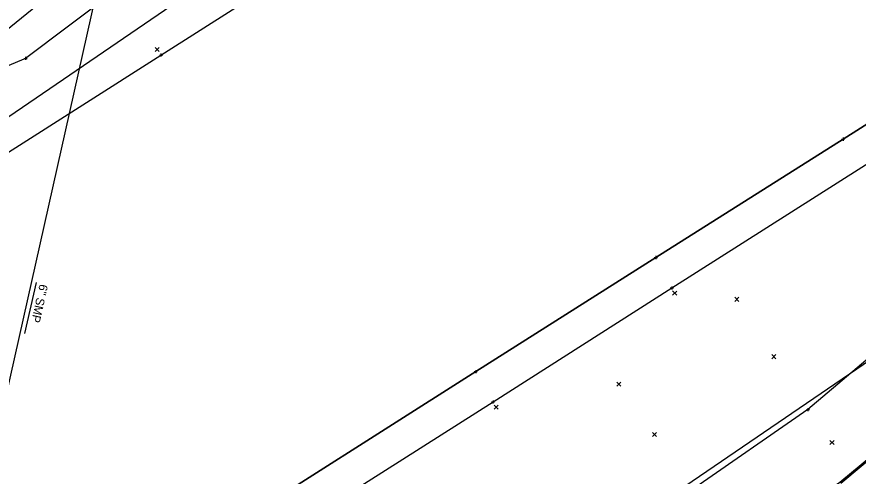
# Model space of a CAD drawing. Extents: x 142461 to 147261, y 511126 to 514697.
# Drawn here: x 145010.2 to 145282.5, y 513225.2 to 513373.9 of the extents above; entities that cross this region are included whole.
import ezdxf

# ---------------------------------------------------------------- set-up
doc = ezdxf.new("R2010")
doc.units = 0
for name, color, linetype in [('DR_X_Storm_Sewer', 7, 'Continuous'), ('PM_X_Surveyed_Line', 7, 'Continuous'), ('PV_X_Curb', 7, 'Continuous'), ('PV_X_EOP', 7, 'Continuous'), ('SV_X_Original_Ground', 7, 'Continuous'), ('SV_X_Random_Point', 7, 'Continuous'), ('SV_X_Shot_Marker', 7, 'Continuous'), ('SV_X_Toe_of_Slope', 7, 'Continuous'), ('UT_X_Sanitary_Line', 7, 'Continuous'), ('UT_X_Sanitary_Text', 7, 'Continuous')]:
    doc.layers.add(name, color=color, linetype=linetype)

msp = doc.modelspace()

# ---------------------------------------------------------------- linework, layer by layer
at = {"layer": 'DR_X_Storm_Sewer'}
msp.add_line((145313.55, 513281.39), (144904.71, 513002.46), dxfattribs=at)
at = {"layer": 'PM_X_Surveyed_Line'}
for points in [[(145071.95, 513203.81), (145158.73, 513259.05), (145217.02, 513295.98), (145277.61, 513334.31), (145360.24, 513386.81), (145456.59, 513448.28), (145523.93, 513491.08), (145564.47, 513516.91), (145634.3, 513561.26), (145696.38, 513600.68), (145817.65, 513677.73), (145914.61, 513739.23), (145999.16, 513793.04), (146085.16, 513848.04), (146162.9, 513897.7)], [(144863.53, 513255.94), (144992.11, 513357.76), (145033.02, 513390.91), (145129.2, 513471.78), (145199.04, 513531.8), (145259.33, 513584.12)]]:
    msp.add_lwpolyline(points, dxfattribs=at)
at = {"layer": 'PV_X_Curb'}
msp.add_lwpolyline([(144906.62, 512975.04), (144910.56, 512977.96), (144915.88, 512983.2), (144920.32, 512988.51), (144935.68, 513005.16), (144948.67, 513014.13), (144965.59, 513024.78), (145041.73, 513073.1), (145115.39, 513119.87), (145203.02, 513175.49), (145259.95, 513211.93), (145276.5, 513223.26), (145307.25, 513248.71)], dxfattribs=at)
at = {"layer": 'PV_X_EOP'}
for points in [[(145289.66, 513607.81), (145278.01, 513598.6), (145276.66, 513600.17), (145272.01, 513596.3), (145273.34, 513594.61), (145259.72, 513582.73), (145259.85, 513578.53), (145241.47, 513552.18), (145207.57, 513522.52), (145136.67, 513462.42), (145040.82, 513381.46), (145013.06, 513360.46), (145002.34, 513355.98), (144995.52, 513354.02), (144864.91, 513253.13), (144870.59, 513243.84), (144959.33, 513299.47), (145056.87, 513361.54), (145139.95, 513414.46), (145215.58, 513462.65), (145285.89, 513507.37)], [(145077.85, 513194.39), (145164.32, 513249.25), (145222.19, 513286.13), (145283.63, 513325.22), (145365.47, 513377.29), (145463.26, 513439.36), (145529.61, 513481.59), (145570.99, 513508.06), (145641.07, 513552.61), (145701.66, 513591.09), (145707.87, 513582.42), (145694.27, 513572.24), (145650.17, 513538.55), (145586.89, 513488.18), (145548.03, 513456.98), (145542.88, 513462.1), (145483.99, 513414.69), (145394.03, 513338.24), (145329.88, 513282.56), (145316.15, 513265.34), (145308.5, 513249.32), (145276.87, 513222.85)]]:
    msp.add_lwpolyline(points, dxfattribs=at)
at = {"layer": 'SV_X_Original_Ground'}
for points in [[(144853.86, 513268.93), (144863.53, 513255.94), (144864.91, 513253.13), (144870.59, 513243.84), (144959.33, 513299.47), (145056.87, 513361.54), (145139.95, 513414.46), (145215.58, 513462.65), (145285.89, 513507.37), (145368.16, 513559.73), (145452.44, 513613.25), (145537.78, 513667.71), (145623.97, 513722.57), (145710.71, 513777.95), (145799.7, 513834.74), (145881.69, 513886.93), (145970.86, 513943.75), (146060.64, 514001.13), (146137.55, 514051.63), (146134.78, 514057.05), (146132.28, 514060.58), (146129.15, 514064.67), (146123.97, 514079.6), (146211.14, 514122.87)], [(146162.9, 513897.7), (146085.16, 513848.04), (145999.16, 513793.04), (145914.61, 513739.23), (145817.65, 513677.73), (145696.38, 513600.68), (145634.3, 513561.26), (145564.47, 513516.91), (145523.93, 513491.08), (145456.59, 513448.28), (145360.24, 513386.81), (145277.61, 513334.31), (145217.02, 513295.98), (145158.73, 513259.05), (145071.95, 513203.81)]]:
    msp.add_lwpolyline(points, dxfattribs=at)
at = {"layer": 'SV_X_Random_Point'}
for p, q in [((145054.99, 513362.67), (145056.34, 513363.99)), ((145055, 513364), (145056.32, 513362.65)), ((145222.44, 513283.82), (145223.78, 513285.14)), ((145222.45, 513285.15), (145223.77, 513283.81)), ((145242.56, 513281.77), (145243.89, 513283.1)), ((145242.56, 513283.1), (145243.89, 513281.77)), ((145254.49, 513263.24), (145255.82, 513264.58)), ((145254.49, 513264.58), (145255.82, 513263.24)), ((145204.38, 513254.35), (145205.72, 513255.69)), ((145204.38, 513255.69), (145205.72, 513254.35)), ((145164.64, 513246.91), (145165.98, 513248.23)), ((145164.65, 513248.24), (145165.97, 513246.89)), ((145215.9, 513238.05), (145217.23, 513239.38)), ((145215.9, 513239.38), (145217.23, 513238.05)), ((145273.36, 513235.44), (145274.69, 513236.77)), ((145273.36, 513236.77), (145274.69, 513235.44))]:
    msp.add_line(p, q, dxfattribs=at)
at = {"layer": 'SV_X_Shot_Marker'}
for p, q in [((145056.37, 513361.54), (145057.37, 513361.53)), ((145056.88, 513362.04), (145056.87, 513361.04)), ((145056.87, 513361.54), (145056.87, 513361.54)), ((145012.56, 513360.46), (145013.56, 513360.45)), ((145013.06, 513360.96), (145013.05, 513359.96)), ((145013.06, 513360.46), (145013.06, 513360.46)), ((145277.11, 513334.31), (145278.11, 513334.3)), ((145277.62, 513334.81), (145277.61, 513333.81)), ((145277.61, 513334.31), (145277.61, 513334.31)), ((145216.52, 513295.98), (145217.52, 513295.97)), ((145217.02, 513296.48), (145217.01, 513295.48)), ((145217.02, 513295.98), (145217.02, 513295.98)), ((145221.69, 513286.14), (145222.69, 513286.13)), ((145222.19, 513286.63), (145222.18, 513285.63)), ((145222.19, 513286.13), (145222.19, 513286.13)), ((145158.23, 513259.06), (145159.23, 513259.05)), ((145158.74, 513259.55), (145158.73, 513258.55)), ((145158.73, 513259.05), (145158.73, 513259.05)), ((145164.32, 513249.75), (145164.31, 513248.75)), ((145163.82, 513249.26), (145164.82, 513249.25)), ((145164.32, 513249.25), (145164.32, 513249.25)), ((145266.24, 513247.27), (145266.24, 513246.27)), ((145265.74, 513246.77), (145266.74, 513246.77)), ((145266.24, 513246.77), (145266.24, 513246.77))]:
    msp.add_line(p, q, dxfattribs=at)
at = {"layer": 'SV_X_Toe_of_Slope'}
for points in [[(145536.33, 513468.51), (145487.34, 513431.87), (145445.96, 513398.71), (145400.54, 513359.53), (145354.59, 513321.64), (145305.79, 513280.24), (145266.24, 513246.77), (145228.58, 513220.65), (145175.08, 513189.66), (145126.31, 513155.94), (145081.98, 513127.67), (145034.97, 513097.1), (144983.36, 513063.49), (144934.41, 513028.84), (144889.77, 512994.77), (144833.63, 512962.42), (144772.97, 512934.59), (144716.73, 512910.04), (144663.56, 512886.77), (144614.86, 512866.63), (144547.92, 512838.93)], [(144902.12, 513271.86), (144957.85, 513307.93), (145007.68, 513341.58), (145062.42, 513379.03), (145111.52, 513415.75)]]:
    msp.add_lwpolyline(points, dxfattribs=at)
at = {"layer": 'UT_X_Sanitary_Line'}
msp.add_line((145049.95, 513443.91), (144977.14, 513120), dxfattribs=at)
at = {"layer": 'UT_X_Sanitary_Text'}
msp.add_line((145012.87, 513271.41), (145016.57, 513287.87), dxfattribs=at)

# ---------------------------------------------------------------- texts
msp.add_text('6" SMP', height=2.8, rotation=257.333, dxfattribs=at).set_placement((145017.62, 513287.52))

doc.saveas('drawing.dxf')
